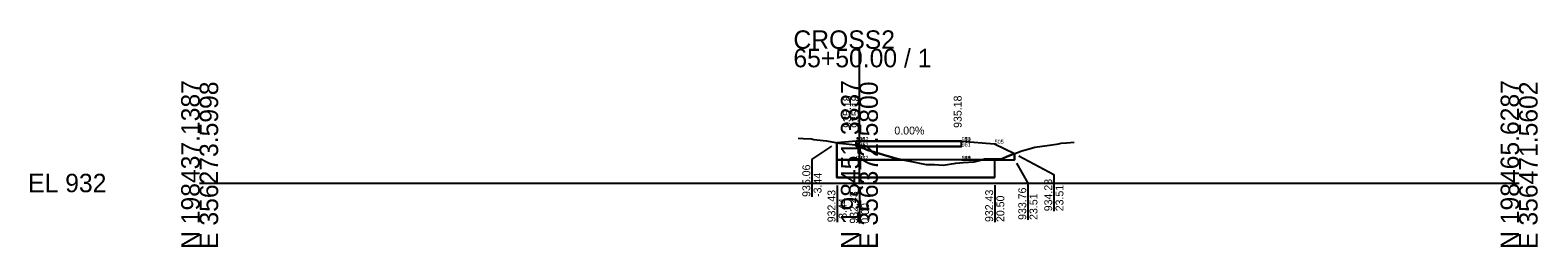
# Model space of a CAD drawing. Extents: x -26 to 203, y -10 to 14021.
# Drawn here: x -25.7 to 202.8, y 6490.3 to 6523.2 of the extents above; entities that cross this region are included whole.
import ezdxf

# ---------------------------------------------------------------- set-up
doc = ezdxf.new("R2010")
doc.units = 0
for name, color, linetype in [('Default', 7, 'Continuous'), ('P_E_XS_Ground', 7, 'Continuous'), ('P_XS', 7, 'Continuous'), ('P_XS_Bold', 7, 'Continuous'), ('P_XS_EAR_CommonGrnd', 7, 'Continuous'), ('P_XS_Lane', 7, 'Continuous'), ('P_XS_Rock', 7, 'Continuous')]:
    doc.layers.add(name, color=color, linetype=linetype)

msp = doc.modelspace()

# ---------------------------------------------------------------- linework, layer by layer
at = {"layer": 'Default'}
for p, q in [((100, 6500), (100, 6520.36)), ((0, 6500), (100, 6500)), ((100, 6500), (200, 6500))]:
    msp.add_line(p, q, dxfattribs=at)
at = {"layer": 'P_E_XS_Ground'}
for p, q in [((90.72, 6506.79), (91.5, 6506.76)), ((91.5, 6506.76), (92.74, 6506.7)), ((92.74, 6506.7), (93.1, 6506.61)), ((93.1, 6506.61), (93.54, 6506.55)), ((93.54, 6506.55), (95.01, 6506.39)), ((95.01, 6506.39), (96.96, 6506.06)), ((96.96, 6506.06), (98.02, 6505.96)), ((98.02, 6505.96), (99.37, 6505.79)), ((99.37, 6505.79), (100, 6505.52)), ((100, 6505.52), (101.28, 6504.99)), ((101.28, 6504.99), (103.68, 6504.27)), ((103.68, 6504.27), (105.71, 6503.68)), ((121.5, 6503.64), (122.64, 6504.14)), ((122.64, 6504.14), (124.62, 6504.87)), ((124.62, 6504.87), (125.76, 6505.19)), ((125.76, 6505.19), (126.6, 6505.45)), ((126.6, 6505.45), (128.45, 6505.7)), ((128.45, 6505.7), (129.86, 6505.89)), ((129.86, 6505.89), (130.17, 6505.95)), ((130.17, 6505.95), (130.61, 6506.04)), ((130.61, 6506.04), (131.41, 6506.09)), ((131.41, 6506.09), (132.57, 6506.21)), ((105.71, 6503.68), (107.63, 6503.33)), ((107.63, 6503.33), (110.1, 6502.81)), ((110.1, 6502.81), (111.38, 6502.82)), ((111.38, 6502.82), (112.69, 6502.73)), ((112.69, 6502.73), (114.64, 6503.01)), ((114.64, 6503.01), (115.74, 6503.11)), ((115.74, 6503.11), (117.41, 6503.21)), ((117.41, 6503.21), (118.94, 6503.6)), ((118.94, 6503.6), (121.5, 6503.64))]:
    msp.add_line(p, q, dxfattribs=at)
at = {"layer": 'P_XS'}
for p, q in [((99.5, 6505.52), (99.5, 6506.36)), ((115.5, 6505.52), (115.5, 6506.36)), ((96.56, 6506.12), (96.56, 6503.52)), ((99.5, 6505.52), (100, 6505.52)), ((115.5, 6505.52), (100, 6505.52)), ((123.51, 6504.46), (123.51, 6503.52)), ((96.56, 6503.52), (100, 6503.52)), ((96.56, 6503.52), (96.56, 6500.86)), ((115.5, 6503.52), (100, 6503.52)), ((115.5, 6503.52), (123.51, 6503.52)), ((120.5, 6503.52), (120.5, 6500.86)), ((96.56, 6500.86), (120.5, 6500.86))]:
    msp.add_line(p, q, dxfattribs=at)
at = {"layer": 'P_XS_EAR_CommonGrnd'}
for points in [[(96.56, 6506.12), (96.96, 6506.06), (98.02, 6505.96), (99.37, 6505.79), (99.5, 6505.73), (99.5, 6506.36)], [(99.5, 6505.73), (100, 6505.52), (115.5, 6505.52), (115.5, 6506.36), (100, 6506.36), (99.5, 6506.36)], [(115.5, 6505.52), (115.5, 6506.36), (120.5, 6505.96), (123.51, 6504.46), (122.64, 6504.14), (121.5, 6503.64), (118.94, 6503.6), (118.63, 6503.52), (115.5, 6503.52), (106.54, 6503.52), (105.71, 6503.68), (103.68, 6504.27), (101.28, 6504.99), (100, 6505.52)], [(99.5, 6505.52), (100, 6505.52), (101.28, 6504.99), (103.68, 6504.27), (105.71, 6503.68), (106.54, 6503.52), (100, 6503.52), (96.56, 6503.52), (96.56, 6506.12), (96.96, 6506.06), (98.02, 6505.96), (99.37, 6505.79), (99.5, 6505.73)], [(99.5, 6505.52), (100, 6505.52), (99.5, 6505.73)], [(120.5, 6503.52), (123.51, 6503.52), (123.51, 6504.46), (122.64, 6504.14), (121.5, 6503.64), (118.94, 6503.6), (118.63, 6503.52)], [(106.54, 6503.52), (107.63, 6503.33), (110.1, 6502.81), (111.38, 6502.82), (112.69, 6502.73), (114.64, 6503.01), (115.74, 6503.11), (117.41, 6503.21), (118.63, 6503.52), (120.5, 6503.52), (120.5, 6500.86), (96.56, 6500.86), (96.56, 6503.52), (100, 6503.52)], [(106.54, 6503.52), (107.63, 6503.33), (110.1, 6502.81), (111.38, 6502.82), (112.69, 6502.73), (114.64, 6503.01), (115.74, 6503.11), (117.41, 6503.21), (118.63, 6503.52), (115.5, 6503.52)]]:
    msp.add_lwpolyline(points, close=True, dxfattribs=at)
at = {"layer": 'P_XS_Lane'}
for p, q in [((99.5, 6506.36), (96.56, 6506.12)), ((99.5, 6506.36), (100, 6506.36)), ((100, 6506.36), (115.5, 6506.36)), ((115.5, 6506.36), (120.5, 6505.96)), ((120.5, 6505.96), (123.51, 6504.46))]:
    msp.add_line(p, q, dxfattribs=at)
at = {"layer": 'P_XS_Rock'}
for p, q in [((92.81, 6503.58), (95.8, 6505.61)), ((124.19, 6504.1), (129.48, 6501.3)), ((92.81, 6503.58), (92.81, 6497.89)), ((123.8, 6503.01), (125.54, 6500)), ((96.62, 6499.63), (96.62, 6494.04)), ((120.52, 6499.68), (120.52, 6494.08)), ((125.54, 6500), (125.54, 6494.4)), ((129.48, 6501.3), (129.48, 6495.71)), ((100, 6499.43), (100, 6493.83))]:
    msp.add_line(p, q, dxfattribs=at)

# ---------------------------------------------------------------- texts
at = {"layer": 'Default'}
for s, p in [('CROSS2', (90, 6520.36)), ('65+50.00 / 1', (90, 6517.56)), ('EL 932', (-26, 6498.6))]:
    msp.add_text(s, height=2.8, dxfattribs=at).set_placement(p)
for s, p in [('N 198437.1387', (0, 6490)), ('E 356273.5998', (2.8, 6490)), ('N 198451.3837', (100, 6490)), ('E 356372.5800', (102.8, 6490)), ('N 198465.6287', (200, 6490)), ('E 356471.5602', (202.8, 6490))]:
    msp.add_text(s, height=2.8, rotation=90, dxfattribs=at).set_placement(p)
at = {"layer": 'P_XS_Bold'}
for s, p in [('951', (99.5, 6506.36)), ('9', (99.5, 6506.36)), ('900', (99.5, 6506.36)), ('952', (100, 6506.36)), ('952', (100, 6506.36)), ('951', (115.5, 6506.36)), ('9', (115.5, 6506.36)), ('900', (115.5, 6506.36)), ('910', (115.5, 6506.36)), ('505', (120.5, 6505.96)), ('961', (99.5, 6505.52)), ('971', (99.5, 6503.52)), ('998', (99.5, 6503.52)), ('962', (100, 6505.52)), ('962', (100, 6505.52)), ('972', (100, 6503.52)), ('972', (100, 6503.52)), ('540', (115.5, 6503.52)), ('961', (115.5, 6505.52)), ('971', (115.5, 6503.52)), ('998', (115.5, 6503.52))]:
    msp.add_text(s, height=0.6, dxfattribs=at).set_placement(p)
at = {"layer": 'P_XS_Rock'}
for s, p in [('935.18', (98.71, 6508.38)), ('935.18', (100, 6508.36)), ('935.18', (100, 6508.36)), ('935.18', (100, 6508.36)), ('935.18', (100, 6508.36)), ('935.18', (115.5, 6508.36)), ('935.06', (92.56, 6497.89)), ('-3.44', (94.26, 6497.89)), ('934.23', (129.23, 6495.71)), ('23.51', (130.93, 6495.71)), ('932.43', (96.37, 6494.04)), ('-3.44', (98.07, 6494.04)), ('932.43', (99.75, 6493.83)), ('932.43', (120.27, 6494.08)), ('20.50', (121.97, 6494.08)), ('933.76', (125.29, 6494.4)), ('23.51', (126.99, 6494.4)), ('0.00', (101.45, 6493.83))]:
    msp.add_text(s, height=1.2, rotation=90, dxfattribs=at).set_placement(p)
msp.add_text('0.00%', height=1.2, dxfattribs=at).set_placement((105.3, 6507.36))

doc.saveas('drawing.dxf')
